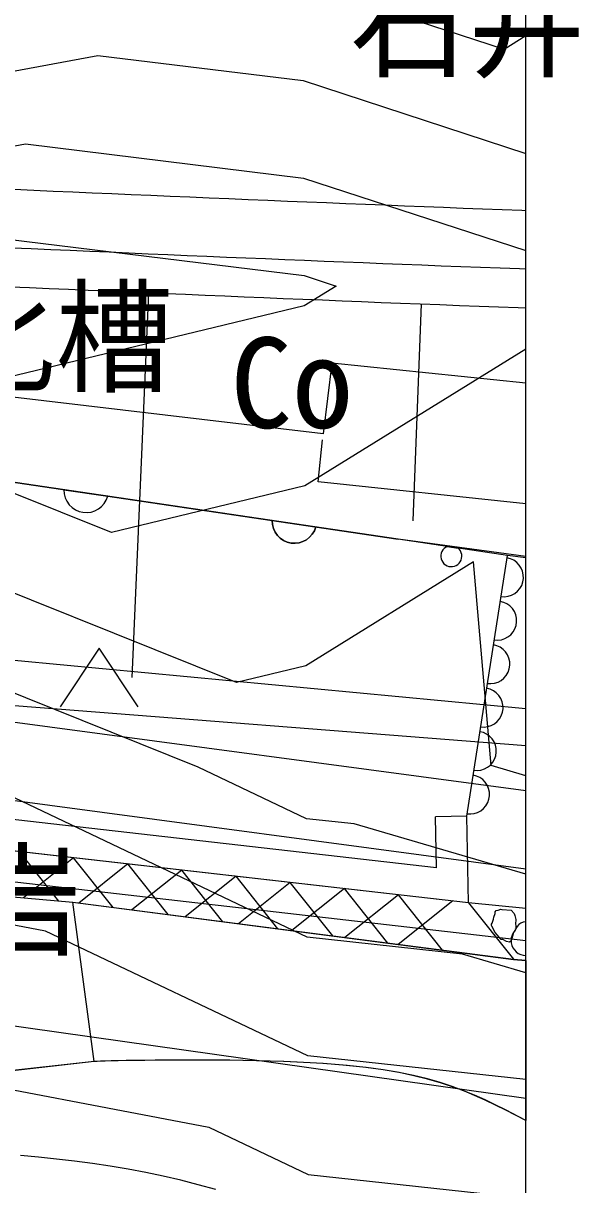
# Model space of a CAD drawing. Extents: x 42655 to 43811, y -141820 to -141156.
# Drawn here: x 43679.37 to 43686.51, y -141366.92 to -141352.02 of the extents above; entities that cross this region are included whole.
import ezdxf

# ---------------------------------------------------------------- set-up
doc = ezdxf.new("R2010")
doc.units = 0
for name, color, linetype in [('D-TTL', 7, 'Continuous'), ('Default', 7, 'Continuous'), ('ZE_HICN', 7, 'Continuous'), ('ZE_LWCN', 7, 'Continuous'), ('地形', 7, 'Continuous'), ('現況水路ﾊｯﾁ', 7, 'Continuous')]:
    doc.layers.add(name, color=color, linetype=linetype)

# ---------------------------------------------------------------- blocks, each defined once
blk = doc.blocks.new('POINT_DISPLAY')
at = {"layer": 'Default'}
blk.add_line((0, 0), (0, 0), dxfattribs=at)

msp = doc.modelspace()

# ---------------------------------------------------------------- linework, layer by layer
at = {"layer": 'D-TTL'}
msp.add_lwpolyline([(42724.63, -141820.399), (43685.83, -141820.386), (43685.821, -141155.586), (42724.621, -141155.599), (42724.63, -141820.399)], dxfattribs=at)
at = {"layer": 'ZE_HICN'}
msp.add_lwpolyline([(43685.824, -141364.203), (43685.014, -141363.966), (43683.017, -141363.748), (43678.456, -141361.579), (43677.917, -141361.363), (43677.737, -141361.364), (43672.822, -141359.766), (43670.166, -141358.665), (43667.725, -141358.014)], dxfattribs=at)
at = {"layer": 'ZE_LWCN'}
for points in [[(43685.824, -141362.94), (43683.62, -141362.293), (43683.01, -141362.227), (43681.616, -141361.564), (43677.911, -141360.079), (43676.671, -141360.085), (43672.817, -141358.833), (43670.736, -141357.969), (43667.721, -141357.165), (43664.978, -141355.48), (43663.603, -141350.537), (43667.692, -141351.097), (43670.39, -141352.194), (43672.781, -141351.308), (43674.456, -141351.3), (43677.873, -141351.924), (43681.259, -141351.298), (43682.959, -141351.507), (43685.549, -141352.353), (43685.824, -141352.179)], [(43685.824, -141361.676), (43685.381, -141361.546), (43685.153, -141358.933), (43683, -141360.265), (43682.108, -141360.48), (43677.905, -141358.796), (43675.605, -141358.806), (43672.813, -141357.899), (43671.305, -141357.273), (43667.717, -141356.316), (43666.345, -141355.474), (43665.658, -141353.002), (43667.703, -141353.282), (43669.051, -141353.831), (43672.787, -141352.447), (43675.401, -141352.435), (43677.877, -141352.887), (43680.33, -141352.433), (43682.965, -141352.757), (43685.824, -141353.691)], [(43671.874, -141356.578), (43667.713, -141355.467), (43672.792, -141353.586), (43676.347, -141353.57), (43677.882, -141353.849), (43679.402, -141353.569), (43682.971, -141354.007), (43685.824, -141354.939)], [(43672.443, -141355.882), (43670.835, -141355.453), (43672.798, -141354.726), (43677.293, -141354.704), (43677.886, -141354.812), (43678.474, -141354.704), (43682.977, -141355.257), (43683.392, -141355.393), (43682.978, -141355.649), (43678.9, -141356.631), (43677.893, -141356.228), (43673.473, -141356.249), (43672.804, -141356.031), (43672.443, -141355.882)], [(43685.824, -141356.202), (43682.989, -141357.957), (43680.504, -141358.556), (43677.899, -141357.512), (43674.539, -141357.528), (43672.808, -141356.965), (43671.874, -141356.578)], [(43685.824, -141365.575), (43683.024, -141365.27), (43679.659, -141363.67), (43677.927, -141363.339), (43676.909, -141362.816), (43675.572, -141361.593), (43672.826, -141360.7), (43669.597, -141359.361), (43667.729, -141358.863)], [(43667.733, -141359.712), (43669.028, -141360.057), (43672.764, -141361.606), (43672.831, -141361.684), (43675.693, -141364.303), (43677.937, -141365.457), (43681.756, -141366.185), (43683.031, -141366.792), (43685.824, -141367.096)]]:
    msp.add_lwpolyline(points, dxfattribs=at)
at = {"layer": '地形'}
for p, q in [((43680.77, -141360.415), (43680.983, -141355.479)), ((43684.483, -141355.622), (43684.376, -141358.406)), ((43676.317, -141357.479), (43684.184, -141358.639)), ((43683.158, -141357.904), (43683.216, -141357.368)), ((43685.824, -141358.189), (43683.158, -141357.904)), ((43679.895, -141358.007), (43680.456, -141358.09)), ((43682.567, -141358.401), (43683.128, -141358.484)), ((43685.824, -141358.861), (43684.184, -141358.639)), ((43684.817, -141358.734), (43684.955, -141358.755)), ((43685.066, -141362.195), (43685.588, -141358.85)), ((43685.824, -141358.881), (43685.588, -141358.85)), ((43680.347, -141360.04), (43679.847, -141360.79)), ((43680.847, -141360.79), (43680.347, -141360.04)), ((43685.824, -141361.868), (43675.463, -141360.483)), ((43685.824, -141361.29), (43675.463, -141360.483)), ((43685.824, -141362.876), (43675.417, -141361.486)), ((43685.066, -141362.195), (43684.666, -141362.203)), ((43684.68, -141362.856), (43684.666, -141362.203)), ((43685.089, -141363.305), (43685.066, -141362.195)), ((43685.089, -141363.305), (43676.339, -141362.309)), ((43685.824, -141363.795), (43675.367, -141362.595)), ((43679.827, -141363.283), (43679.323, -141362.649)), ((43680.019, -141362.728), (43679.373, -141363.242)), ((43680.526, -141363.366), (43680.019, -141362.728)), ((43680.714, -141362.807), (43680.084, -141363.309)), ((43681.231, -141363.457), (43680.714, -141362.807)), ((43681.41, -141362.887), (43680.768, -141363.397)), ((43681.936, -141363.549), (43681.41, -141362.887)), ((43682.105, -141362.966), (43681.452, -141363.486)), ((43682.642, -141363.64), (43682.105, -141362.966)), ((43682.801, -141363.045), (43682.135, -141363.574)), ((43683.347, -141363.731), (43682.801, -141363.045)), ((43683.496, -141363.124), (43682.819, -141363.663)), ((43684.052, -141363.822), (43683.496, -141363.124)), ((43684.192, -141363.203), (43683.503, -141363.751)), ((43684.887, -141363.282), (43684.187, -141363.84)), ((43684.757, -141363.914), (43684.192, -141363.203)), ((43680.283, -141365.341), (43680.009, -141363.299)), ((43685.824, -141365.818), (43673.517, -141364.076))]:
    msp.add_line(p, q, dxfattribs=at)
for points in [[(43679.257, -141354.152), (43679.508, -141354.163), (43679.758, -141354.174), (43680.008, -141354.185), (43680.258, -141354.196), (43680.509, -141354.207), (43680.759, -141354.218), (43681.009, -141354.229), (43681.26, -141354.239), (43681.51, -141354.25), (43681.761, -141354.261), (43682.011, -141354.271), (43682.262, -141354.282), (43682.512, -141354.292), (43682.763, -141354.302), (43683.014, -141354.313), (43683.264, -141354.323), (43683.515, -141354.333), (43683.766, -141354.343), (43684.016, -141354.353), (43684.267, -141354.363), (43684.518, -141354.373), (43684.769, -141354.382), (43685.02, -141354.392), (43685.271, -141354.401), (43685.522, -141354.411), (43685.773, -141354.42), (43685.824, -141354.422)], [(43679.224, -141354.901), (43679.474, -141354.912), (43679.725, -141354.923), (43679.975, -141354.934), (43680.225, -141354.945), (43680.476, -141354.956), (43680.726, -141354.967), (43680.977, -141354.978), (43681.228, -141354.989), (43681.478, -141354.999), (43681.729, -141355.01), (43681.98, -141355.021), (43682.23, -141355.031), (43682.481, -141355.041), (43682.732, -141355.052), (43682.983, -141355.062), (43683.234, -141355.072), (43683.485, -141355.082), (43683.736, -141355.092), (43683.987, -141355.102), (43684.238, -141355.112), (43684.489, -141355.122), (43684.74, -141355.132), (43684.991, -141355.141), (43685.243, -141355.151), (43685.494, -141355.16), (43685.745, -141355.169), (43685.824, -141355.172)], [(43679.202, -141355.401), (43679.452, -141355.412), (43679.703, -141355.423), (43679.953, -141355.434), (43680.204, -141355.445), (43680.454, -141355.456), (43680.705, -141355.467), (43680.955, -141355.477), (43681.206, -141355.488), (43681.457, -141355.499), (43681.708, -141355.509), (43681.959, -141355.52), (43682.209, -141355.531), (43682.46, -141355.541), (43682.711, -141355.551), (43682.962, -141355.562), (43683.213, -141355.572), (43683.465, -141355.582), (43683.716, -141355.592), (43683.967, -141355.602), (43684.218, -141355.612), (43684.47, -141355.622), (43684.721, -141355.631), (43684.972, -141355.641), (43685.224, -141355.65), (43685.475, -141355.66), (43685.727, -141355.669), (43685.824, -141355.672)], [(43685.824, -141356.64), (43683.336, -141356.381), (43683.223, -141357.288), (43674.016, -141356.204)], [(43685.588, -141358.85), (43684.184, -141358.639), (43676.168, -141357.458)], [(43680.456, -141358.09), (43680.456, -141358.09), (43679.895, -141358.007), (43679.895, -141358.007)], [(43679.895, -141358.007), (43679.899, -141358.059), (43679.912, -141358.109), (43679.933, -141358.155), (43679.963, -141358.198), (43680, -141358.234), (43680.042, -141358.263), (43680.089, -141358.284), (43680.139, -141358.296), (43680.191, -141358.299), (43680.242, -141358.292), (43680.291, -141358.277), (43680.337, -141358.253), (43680.377, -141358.221), (43680.411, -141358.182), (43680.438, -141358.138), (43680.456, -141358.09)], [(43679.895, -141358.007), (43679.899, -141358.059), (43679.912, -141358.109), (43679.933, -141358.155), (43679.963, -141358.198), (43680, -141358.234), (43680.042, -141358.263), (43680.089, -141358.284), (43680.139, -141358.296), (43680.191, -141358.299), (43680.242, -141358.292), (43680.291, -141358.277), (43680.337, -141358.253), (43680.377, -141358.221), (43680.411, -141358.182), (43680.438, -141358.138), (43680.456, -141358.09)], [(43682.567, -141358.401), (43682.567, -141358.401), (43683.128, -141358.484), (43683.128, -141358.484)], [(43683.128, -141358.484), (43683.11, -141358.532), (43683.083, -141358.576), (43683.049, -141358.615), (43683.009, -141358.647), (43682.963, -141358.671), (43682.914, -141358.686), (43682.863, -141358.693), (43682.811, -141358.69), (43682.761, -141358.678), (43682.714, -141358.657), (43682.671, -141358.628), (43682.635, -141358.592), (43682.605, -141358.549), (43682.584, -141358.503), (43682.571, -141358.453), (43682.567, -141358.401)], [(43682.567, -141358.401), (43682.571, -141358.453), (43682.584, -141358.503), (43682.605, -141358.549), (43682.635, -141358.592), (43682.671, -141358.628), (43682.714, -141358.657), (43682.761, -141358.678), (43682.811, -141358.69), (43682.863, -141358.693), (43682.914, -141358.686), (43682.963, -141358.671), (43683.009, -141358.647), (43683.049, -141358.615), (43683.083, -141358.576), (43683.11, -141358.532), (43683.128, -141358.484)], [(43684.817, -141358.734), (43684.795, -141358.746), (43684.776, -141358.761), (43684.76, -141358.779), (43684.748, -141358.799), (43684.739, -141358.822), (43684.735, -141358.845), (43684.734, -141358.869), (43684.738, -141358.893), (43684.747, -141358.916), (43684.759, -141358.937), (43684.774, -141358.955), (43684.793, -141358.97), (43684.814, -141358.982), (43684.837, -141358.99), (43684.861, -141358.993), (43684.885, -141358.993), (43684.908, -141358.988), (43684.931, -141358.978), (43684.951, -141358.966), (43684.969, -141358.949), (43684.983, -141358.93), (43684.994, -141358.908), (43685.001, -141358.885), (43685.004, -141358.861), (43685.002, -141358.837), (43684.996, -141358.814), (43684.986, -141358.792), (43684.972, -141358.772), (43684.955, -141358.755)], [(43684.817, -141358.734), (43684.795, -141358.746), (43684.776, -141358.761), (43684.76, -141358.779), (43684.748, -141358.799), (43684.739, -141358.822), (43684.735, -141358.845), (43684.734, -141358.869), (43684.738, -141358.893), (43684.747, -141358.916), (43684.759, -141358.937), (43684.774, -141358.955), (43684.793, -141358.97), (43684.814, -141358.982), (43684.837, -141358.99), (43684.861, -141358.993), (43684.885, -141358.993), (43684.908, -141358.988), (43684.931, -141358.978), (43684.951, -141358.966), (43684.969, -141358.949), (43684.983, -141358.93), (43684.994, -141358.908), (43685.001, -141358.885), (43685.004, -141358.861), (43685.002, -141358.837), (43684.996, -141358.814), (43684.986, -141358.792), (43684.972, -141358.772), (43684.955, -141358.755)], [(43684.955, -141358.755), (43684.955, -141358.755), (43684.817, -141358.734), (43684.817, -141358.734)], [(43685.506, -141359.376), (43685.552, -141359.379), (43685.598, -141359.373), (43685.642, -141359.359), (43685.683, -141359.337), (43685.719, -141359.309), (43685.749, -141359.273), (43685.772, -141359.234), (43685.787, -141359.19), (43685.794, -141359.144), (43685.793, -141359.098), (43685.783, -141359.053), (43685.765, -141359.011), (43685.74, -141358.972), (43685.708, -141358.939), (43685.67, -141358.912), (43685.628, -141358.893), (43685.583, -141358.882)], [(43685.089, -141363.305), (43676.339, -141362.309), (43673.61, -141361.434), (43673.349, -141359.511)], [(43684.68, -141362.856), (43676.423, -141361.916), (43673.972, -141361.13), (43673.745, -141359.457)], [(43685.419, -141359.933), (43685.465, -141359.936), (43685.511, -141359.931), (43685.555, -141359.917), (43685.595, -141359.895), (43685.631, -141359.866), (43685.661, -141359.831), (43685.685, -141359.791), (43685.7, -141359.748), (43685.707, -141359.702), (43685.706, -141359.656), (43685.696, -141359.611), (43685.678, -141359.568), (43685.652, -141359.53), (43685.62, -141359.497), (43685.583, -141359.47), (43685.541, -141359.451), (43685.496, -141359.439)], [(43675.492, -141359.838), (43685.824, -141360.815)], [(43685.332, -141360.491), (43685.378, -141360.494), (43685.424, -141360.488), (43685.468, -141360.474), (43685.508, -141360.452), (43685.544, -141360.423), (43685.574, -141360.388), (43685.597, -141360.348), (43685.613, -141360.305), (43685.62, -141360.259), (43685.619, -141360.213), (43685.609, -141360.168), (43685.591, -141360.126), (43685.565, -141360.087), (43685.533, -141360.054), (43685.496, -141360.027), (43685.454, -141360.008), (43685.409, -141359.997)], [(43685.245, -141361.048), (43685.291, -141361.051), (43685.337, -141361.045), (43685.381, -141361.032), (43685.421, -141361.01), (43685.457, -141360.981), (43685.487, -141360.946), (43685.51, -141360.906), (43685.526, -141360.862), (43685.533, -141360.817), (43685.531, -141360.771), (43685.522, -141360.726), (43685.504, -141360.683), (43685.478, -141360.645), (43685.446, -141360.612), (43685.409, -141360.585), (43685.367, -141360.565), (43685.322, -141360.554)], [(43685.158, -141361.606), (43685.204, -141361.609), (43685.249, -141361.603), (43685.293, -141361.589), (43685.334, -141361.567), (43685.37, -141361.538), (43685.4, -141361.503), (43685.423, -141361.463), (43685.439, -141361.42), (43685.446, -141361.374), (43685.444, -141361.328), (43685.435, -141361.283), (43685.417, -141361.241), (43685.391, -141361.202), (43685.359, -141361.169), (43685.321, -141361.142), (43685.28, -141361.123), (43685.235, -141361.112)], [(43685.071, -141362.163), (43685.117, -141362.166), (43685.162, -141362.16), (43685.206, -141362.146), (43685.247, -141362.125), (43685.283, -141362.096), (43685.313, -141362.061), (43685.336, -141362.021), (43685.352, -141361.977), (43685.359, -141361.932), (43685.357, -141361.886), (43685.347, -141361.841), (43685.329, -141361.798), (43685.304, -141361.76), (43685.272, -141361.726), (43685.234, -141361.7), (43685.192, -141361.68), (43685.148, -141361.669)], [(43676.109, -141362.95), (43680.009, -141363.299), (43685.665, -141364.031)], [(43685.824, -141363.377), (43685.089, -141363.305), (43685.665, -141364.031), (43685.824, -141364.044)], [(43685.521, -141363.391), (43685.636, -141363.399), (43685.677, -141363.443), (43685.682, -141363.469), (43685.698, -141363.518), (43685.694, -141363.58), (43685.695, -141363.595), (43685.695, -141363.622), (43685.691, -141363.647), (43685.665, -141363.689), (43685.655, -141363.734), (43685.648, -141363.749), (43685.642, -141363.778), (43685.631, -141363.799), (43685.616, -141363.81), (43685.575, -141363.802), (43685.528, -141363.778), (43685.509, -141363.778), (43685.459, -141363.715), (43685.432, -141363.688), (43685.388, -141363.605), (43685.384, -141363.595), (43685.386, -141363.582), (43685.394, -141363.567), (43685.411, -141363.517), (43685.415, -141363.491), (43685.43, -141363.444), (43685.432, -141363.422), (43685.445, -141363.406), (43685.47, -141363.401), (43685.481, -141363.398), (43685.5, -141363.389), (43685.516, -141363.392), (43685.521, -141363.391)], [(43685.824, -141363.549), (43685.793, -141363.555), (43685.763, -141363.567), (43685.736, -141363.585), (43685.713, -141363.608), (43685.695, -141363.635), (43685.682, -141363.665)], [(43685.682, -141363.665), (43685.662, -141363.692), (43685.648, -141363.722), (43685.638, -141363.754), (43685.635, -141363.787), (43685.637, -141363.821), (43685.645, -141363.853), (43685.659, -141363.884), (43685.678, -141363.911), (43685.701, -141363.935), (43685.728, -141363.955), (43685.759, -141363.969), (43685.791, -141363.978), (43685.824, -141363.981)], [(43680.283, -141365.341), (43679.043, -141365.478)], [(43685.824, -141366.098), (43685.564, -141365.963), (43685.433, -141365.898), (43685.301, -141365.835), (43685.166, -141365.775), (43685.026, -141365.718), (43684.88, -141365.664), (43684.725, -141365.613), (43684.561, -141365.566), (43684.385, -141365.523), (43684.196, -141365.484), (43683.992, -141365.449), (43683.771, -141365.418), (43683.531, -141365.392), (43683.378, -141365.379), (43683.219, -141365.368), (43683.055, -141365.358), (43682.886, -141365.349), (43682.715, -141365.342), (43682.541, -141365.336), (43682.367, -141365.332), (43682.193, -141365.328), (43682.02, -141365.326), (43681.849, -141365.324), (43681.682, -141365.323), (43681.519, -141365.323), (43681.362, -141365.323), (43681.211, -141365.324), (43681.067, -141365.326), (43680.932, -141365.327), (43680.807, -141365.329), (43680.693, -141365.331), (43680.591, -141365.333), (43680.501, -141365.335), (43680.425, -141365.337), (43680.364, -141365.339), (43680.32, -141365.34), (43680.292, -141365.341), (43680.283, -141365.341)], [(43681.845, -141366.983), (43681.62, -141366.923), (43681.395, -141366.866), (43681.17, -141366.814), (43680.944, -141366.767), (43680.717, -141366.724), (43680.489, -141366.685), (43680.26, -141366.651), (43680.031, -141366.621), (43679.8, -141366.594), (43679.569, -141366.57), (43679.337, -141366.55)]]:
    msp.add_lwpolyline(points, dxfattribs=at)
at = {"layer": '現況水路ﾊｯﾁ'}
msp.add_lwpolyline([(43676.109, -141362.95), (43680.009, -141363.299), (43685.668, -141364.034), (43685.824, -141364.047), (43685.824, -141366.099), (43685.567, -141365.966), (43685.436, -141365.901), (43685.304, -141365.838), (43685.168, -141365.778), (43685.029, -141365.72), (43684.882, -141365.666), (43684.728, -141365.616), (43684.564, -141365.567), (43684.388, -141365.524), (43684.199, -141365.484), (43683.992, -141365.449), (43683.774, -141365.419), (43683.474, -141365.388), (43683.222, -141365.368), (43683.058, -141365.358), (43682.889, -141365.349), (43682.718, -141365.342), (43682.544, -141365.336), (43682.37, -141365.332), (43682.196, -141365.328), (43682.023, -141365.326), (43681.852, -141365.324), (43681.685, -141365.323), (43681.522, -141365.323), (43681.364, -141365.323), (43681.213, -141365.324), (43681.07, -141365.326), (43680.935, -141365.327), (43680.755, -141365.33), (43680.55, -141365.334), (43680.398, -141365.338), (43680.283, -141365.341), (43679.046, -141365.481)], dxfattribs=at)

# ---------------------------------------------------------------- block references
at = {"layer": '地形', "xscale": 1200, "yscale": 1200, "rotation": 180}
msp.add_blockref('POINT_DISPLAY', (43685.679, -141363.634), dxfattribs=at)
msp.add_blockref('POINT_DISPLAY', (43685.679, -141363.634), dxfattribs=at)

# ---------------------------------------------------------------- texts
at = {"layer": '地形'}
for s, height, p in [('石井', 1.1606, (43683.575, -141352.589)), ('浄化槽', 1.1606, (43676.768, -141356.629)), ('Co', 1.1606, (43682.032, -141357.213)), ('岩', 1.161, (43678.61, -141363.859))]:
    msp.add_text(s, height=height, dxfattribs=at).set_placement(p)

doc.saveas('drawing.dxf')
